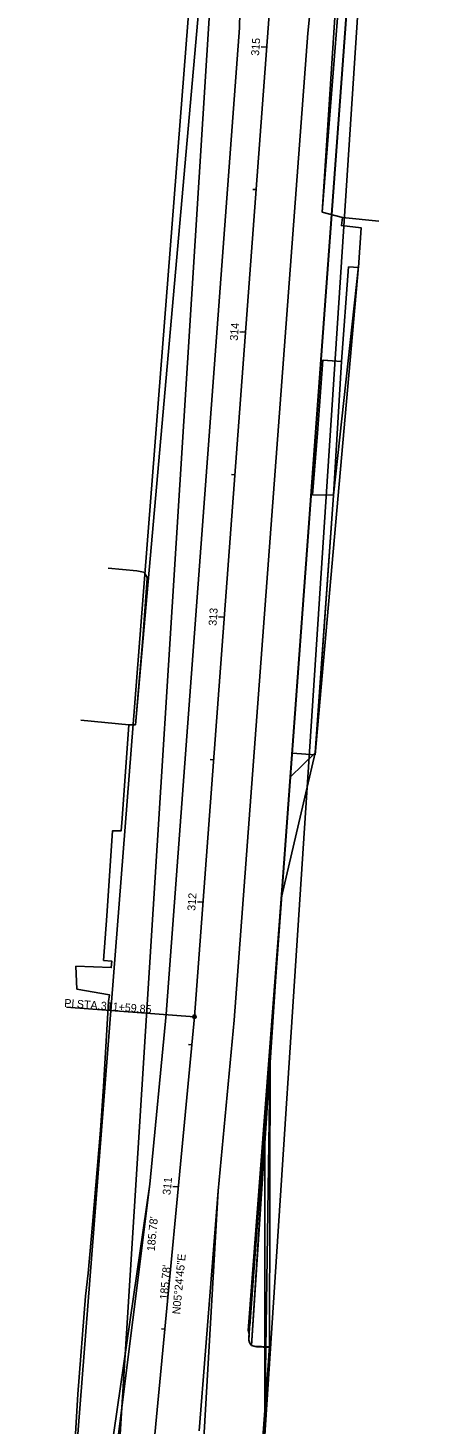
# Model space of a CAD drawing. Extents: x 219353 to 221640, y 361458 to 364236.
# Drawn here: x 220538 to 220684.5, y 362474.7 to 362963.2 of the extents above; entities that cross this region are included whole.
import ezdxf

# ---------------------------------------------------------------- set-up
doc = ezdxf.new("R2010")
doc.units = 0
for name, color, linetype in [('Default', 7, 'Continuous'), ('DR_P_Cells', 7, 'Continuous'), ('DR_P_GenericNode', 7, 'Continuous'), ('DR_X_Cells', 7, 'Continuous'), ('DR_X_GenericNode', 7, 'Continuous'), ('DT_X_Contour_Major', 7, 'Continuous'), ('DT_X_Contour_Minor', 7, 'Continuous'), ('DT_X_Terrain_Boundary', 7, 'Continuous'), ('DT_X_Void', 7, 'Continuous'), ('SC_ProfileRun1', 7, 'Continuous'), ('SC_ProfileRun2', 7, 'Continuous'), ('SC_ProfileRun3', 7, 'Continuous'), ('SC_Scratch1', 7, 'Continuous'), ('UT_X_Sanitary_Cells', 7, 'Continuous')]:
    doc.layers.add(name, color=color, linetype=linetype)

msp = doc.modelspace()

# ---------------------------------------------------------------- linework, layer by layer
at = {"layer": 'Default'}
for p, q in [((220606.11, 362243.12), (220684.52, 363442.47)), ((220684.52, 363442.47), (220615.71, 362509.09)), ((220624.82, 362631.32), (220684.52, 363442.47)), ((220684.52, 363442.47), (220626.15, 362649.27)), ((220641.07, 362898.72), (220684.52, 363442.47)), ((220648.26, 362896.8), (220641.07, 362898.72)), ((220647.83, 362894.02), (220648.26, 362896.8)), ((220654.81, 362893.19), (220647.83, 362894.02)), ((220653.82, 362879.4), (220654.81, 362893.19)), ((220638.7, 362708.88), (220653.85, 362879.85)), ((220653.85, 362879.85), (220645.02, 362799.67)), ((220647.88, 362846.46), (220650.36, 362879.59)), ((220650.36, 362879.59), (220653.82, 362879.4)), ((220645.02, 362799.67), (220647.88, 362846.46)), ((220638.7, 362709.51), (220626.88, 362659.06)), ((220626.88, 362659.06), (220630.64, 362709.49)), ((220630.02, 362701.13), (220638.7, 362709.51)), ((220630.64, 362709.49), (220638.7, 362708.88)), ((220615.19, 362507.4), (220630.02, 362701.13)), ((220626.15, 362649.27), (220615.19, 362507.4)), ((220616.32, 362502.25), (220624.82, 362631.32)), ((220622.88, 362604.84), (220616.32, 362502.25)), ((220621, 362477.12), (220622.88, 362604.84)), ((220622.88, 362604.84), (220622.7, 362501.72)), ((220622.7, 362501.72), (220622.88, 362604.84)), ((220615.71, 362509.09), (220620.96, 362579.91)), ((220620.96, 362579.91), (220621, 362477.12)), ((220615.41, 362504.1), (220615.41, 362505.1))]:
    msp.add_line(p, q, dxfattribs=at)
msp.add_open_spline([(220615.41, 362505.04), (220615.36, 362504.35), (220615.42, 362503.13), (220616.86, 362501.84), (220617.84, 362501.8), (220618.19, 362501.78)], degree=3, dxfattribs=at)
at = {"layer": 'DR_X_Cells'}
msp.add_line((220596.38, 362617.24), (220551.5, 362620.59), dxfattribs=at)
msp.add_circle((220596.38, 362617.24), 0.6, dxfattribs=at)
at = {"layer": 'DR_X_GenericNode'}
for p, q in [((220631.67, 363446.41), (220538.01, 362247.29)), ((220541.47, 362010.88), (220631.67, 363446.41)), ((220612.16, 362963.18), (220613.87, 363053.31)), ((220575.71, 362719.33), (220605.02, 363051.24)), ((220636.09, 362961.4), (220644.78, 363051)), ((220641.07, 362898.72), (220646.21, 362977.69)), ((220586.41, 362618.09), (220612.16, 362963.18)), ((220610.33, 362616.06), (220636.09, 362961.4)), ((220648.26, 362896.8), (220641.07, 362898.72)), ((220647.83, 362894.02), (220648.26, 362896.8)), ((220654.81, 362893.19), (220647.83, 362894.02)), ((220653.82, 362879.4), (220654.81, 362893.19)), ((220647.88, 362846.46), (220650.36, 362879.59)), ((220650.36, 362879.59), (220653.82, 362879.4)), ((220645.02, 362799.67), (220647.88, 362846.46)), ((220638.7, 362709.51), (220645.02, 362799.67)), ((220573.39, 362719.33), (220575.71, 362719.33)), ((220626.88, 362659.06), (220630.64, 362709.49)), ((220630.64, 362709.49), (220638.7, 362708.88)), ((220638.7, 362708.88), (220638.7, 362709.51)), ((220622.88, 362604.84), (220626.88, 362659.06)), ((220580.78, 362558.61), (220586.41, 362618.09)), ((220604.67, 362556.35), (220610.33, 362616.06)), ((220618.61, 362547.99), (220622.88, 362604.84)), ((220562.63, 362433.83), (220580.78, 362558.61)), ((220598.01, 362472.29), (220604.67, 362556.35)), ((220615.19, 362507.4), (220618.61, 362547.99)), ((220615.49, 362506.1), (220615.19, 362507.4)), ((220615.41, 362504.1), (220615.49, 362506.1)), ((220615.76, 362503.06), (220615.41, 362504.1)), ((220616.32, 362502.25), (220615.76, 362503.06)), ((220617.16, 362501.92), (220616.32, 362502.25)), ((220622.7, 362501.72), (220617.16, 362501.92)), ((220622.58, 362500.41), (220622.7, 362501.72)), ((220621, 362477.12), (220622.58, 362500.41)), ((220615.74, 362408.19), (220621, 362477.12))]:
    msp.add_line(p, q, dxfattribs=at)
at = {"layer": 'DT_X_Contour_Major'}
for p, q in [((220596.38, 362617.24), (220663.15, 363512.27)), ((220577.51, 362418.1), (220596.38, 362617.24)), ((220578.85, 362432.29), (220596.38, 362617.24))]:
    msp.add_line(p, q, dxfattribs=at)
at = {"layer": 'DT_X_Contour_Minor'}
for p, q in [((220636.09, 362961.4), (220644.78, 363051)), ((220636.09, 362961.4), (220644.78, 363051)), ((220586.41, 362618.09), (220612.16, 362963.18)), ((220586.41, 362618.09), (220612.16, 362963.18)), ((220586.41, 362618.09), (220612.16, 362963.18)), ((220586.41, 362618.09), (220612.16, 362963.18)), ((220586.41, 362618.09), (220612.16, 362963.18)), ((220610.33, 362616.06), (220636.09, 362961.4)), ((220610.33, 362616.06), (220636.09, 362961.4)), ((220641.59, 362846.95), (220647.88, 362846.46)), ((220645.02, 362799.67), (220637.73, 362799.78)), ((220638.65, 362708.89), (220645.02, 362799.67)), ((220638.65, 362708.89), (220645.02, 362799.67)), ((220628.86, 362685.48), (220630.64, 362709.49)), ((220628.86, 362685.48), (220630.64, 362709.49)), ((220630.64, 362709.49), (220638.65, 362708.89)), ((220630.64, 362709.49), (220638.65, 362708.89)), ((220626.88, 362659.06), (220628.86, 362685.48)), ((220626.88, 362659.06), (220628.86, 362685.48)), ((220624.82, 362631.32), (220626.88, 362659.06)), ((220624.82, 362631.32), (220626.88, 362659.06)), ((220555.18, 362626.91), (220554.83, 362634.86)), ((220622.94, 362605.57), (220624.82, 362631.32)), ((220622.94, 362605.57), (220624.82, 362631.32)), ((220580.78, 362558.61), (220586.41, 362618.09)), ((220580.78, 362558.61), (220586.41, 362618.09)), ((220580.78, 362558.61), (220586.41, 362618.09)), ((220580.78, 362558.61), (220586.41, 362618.09)), ((220580.78, 362558.61), (220586.41, 362618.09)), ((220604.67, 362556.35), (220610.33, 362616.06)), ((220604.67, 362556.35), (220610.33, 362616.06)), ((220620.96, 362579.87), (220622.94, 362605.57)), ((220620.96, 362579.87), (220622.94, 362605.57)), ((220618.81, 362550.62), (220620.96, 362579.87)), ((220618.81, 362550.62), (220620.96, 362579.87)), ((220564.94, 362433.61), (220580.78, 362558.61)), ((220564.94, 362433.61), (220580.78, 362558.61)), ((220564.94, 362433.61), (220580.78, 362558.61)), ((220564.94, 362433.61), (220580.78, 362558.61)), ((220564.94, 362433.61), (220580.78, 362558.61)), ((220597.41, 362430.53), (220604.67, 362556.35)), ((220597.41, 362430.53), (220604.67, 362556.35)), ((220597.41, 362430.53), (220604.67, 362556.35)), ((220616.97, 362525.97), (220618.81, 362550.62)), ((220616.97, 362525.97), (220618.81, 362550.62)), ((220615.41, 362505.04), (220616.97, 362525.97)), ((220615.41, 362505.04), (220616.97, 362525.97)), ((220615.12, 362399.96), (220622.66, 362501.46)), ((220615.12, 362399.96), (220622.66, 362501.46)), ((220622.66, 362501.46), (220618.19, 362501.78)), ((220622.66, 362501.46), (220618.19, 362501.78))]:
    msp.add_line(p, q, dxfattribs=at)
for points in [[(220647.88, 362846.46), (220650.36, 362879.59), (220653.82, 362879.4), (220654.81, 362893.19), (220647.83, 362894.02), (220648.26, 362896.8), (220660.9, 362895.52)], [(220647.88, 362846.46), (220650.36, 362879.59), (220653.82, 362879.4), (220654.81, 362893.19), (220647.83, 362894.02), (220648.26, 362896.8), (220660.9, 362895.52)], [(220645.02, 362799.67), (220637.73, 362799.78), (220639.47, 362821.44), (220641.35, 362846.97), (220647.88, 362846.46)], [(220554.83, 362634.86), (220567.24, 362634.42), (220567.45, 362636.61), (220564.51, 362636.9), (220565.68, 362652.52), (220567.69, 362682.29), (220570.73, 362682.29), (220571.06, 362686.6), (220573.39, 362719.33), (220556.55, 362721.02)], [(220548.97, 362401.87), (220551.9, 362425.19), (220552.11, 362427.73), (220555.49, 362485.14), (220558.19, 362519.47), (220559.13, 362527.53), (220560.7, 362544.5), (220563.39, 362577.56), (220564.51, 362592.82), (220566.29, 362622.53), (220566.62, 362624.87), (220555.18, 362626.91)]]:
    msp.add_lwpolyline(points, dxfattribs=at)
msp.add_open_spline([(220618.19, 362501.78), (220617.84, 362501.8), (220616.86, 362501.84), (220615.42, 362503.13), (220615.36, 362504.35), (220615.41, 362505.04)], degree=3, dxfattribs=at)
msp.add_open_spline([(220618.19, 362501.78), (220617.84, 362501.8), (220616.86, 362501.84), (220615.42, 362503.13), (220615.36, 362504.35), (220615.41, 362505.04)], degree=3, dxfattribs=at)
at = {"layer": 'DT_X_Terrain_Boundary'}
for p, q in [((220576.19, 362773.22), (220566.19, 362774.13)), ((220578.5, 362772.75), (220576.19, 362773.22)), ((220578.29, 362749.55), (220579.83, 362770.51)), ((220575.71, 362719.33), (220578.29, 362749.55))]:
    msp.add_line(p, q, dxfattribs=at)
msp.add_ellipse((220575.86, 362769.63), major_axis=(2.06, 3.53), ratio=0.992635, start_param=5.454232, end_param=6.106412, dxfattribs=at)
at = {"layer": 'DT_X_Void'}
for p, q in [((220630.64, 362709.49), (220628.86, 362685.48)), ((220628.86, 362685.48), (220626.88, 362659.06)), ((220626.88, 362659.06), (220624.82, 362631.32)), ((220624.82, 362631.32), (220622.94, 362605.57)), ((220622.94, 362605.57), (220620.96, 362579.87)), ((220620.96, 362579.87), (220618.81, 362550.62)), ((220618.81, 362550.62), (220616.97, 362525.97)), ((220616.97, 362525.97), (220615.41, 362505.04)), ((220618.19, 362501.78), (220622.66, 362501.46))]:
    msp.add_line(p, q, dxfattribs=at)
at = {"layer": 'SC_ProfileRun2'}
msp.add_line((220596.38, 362617.24), (220551.5, 362620.59), dxfattribs=at)
msp.add_circle((220596.38, 362617.24), 0.6, dxfattribs=at)
at = {"layer": 'SC_ProfileRun3'}
for p, q in [((220621.69, 362956.46), (220619.69, 362956.61)), ((220614.25, 362856.73), (220613.05, 362856.82)), ((220606.81, 362757.01), (220605.61, 362757.1)), ((220599.37, 362657.29), (220598.17, 362657.38)), ((220590.73, 362557.67), (220589.54, 362557.78))]:
    msp.add_line(p, q, dxfattribs=at)
at = {"layer": 'UT_X_Sanitary_Cells'}
for p, q in [((220621.69, 362956.46), (220619.69, 362956.61)), ((220617.97, 362906.6), (220616.77, 362906.68)), ((220614.25, 362856.73), (220612.25, 362856.88)), ((220610.53, 362806.87), (220609.33, 362806.96)), ((220606.81, 362757.01), (220604.81, 362757.16)), ((220603.09, 362707.15), (220601.89, 362707.24)), ((220599.37, 362657.29), (220597.37, 362657.44)), ((220595.45, 362607.44), (220594.25, 362607.56)), ((220590.73, 362557.67), (220588.74, 362557.85)), ((220586.02, 362507.89), (220584.82, 362508))]:
    msp.add_line(p, q, dxfattribs=at)

# ---------------------------------------------------------------- texts
at = {"layer": 'DR_P_Cells'}
msp.add_text("185.78'", height=2.8, rotation=84.5875, dxfattribs=at).set_placement((220586.94, 362518.12))
at = {"layer": 'DR_P_GenericNode'}
msp.add_text("185.78'", height=2.8, rotation=84.5875, dxfattribs=at).set_placement((220582.43, 362535.07))
at = {"layer": 'DR_X_Cells'}
for s, p in [('PI', (220550.66, 362620.7)), (' STA. ', (220554.04, 362620.45)), ('311+59.85', (220563.46, 362619.74))]:
    msp.add_text(s, height=2.8, rotation=355.7333, dxfattribs=at).set_placement(p)
at = {"layer": 'SC_ProfileRun1'}
msp.add_text('N05°24\'45"E', height=2.8, rotation=84.5875, dxfattribs=at).set_placement((220591.32, 362513))
at = {"layer": 'SC_ProfileRun2'}
for s, p in [('PI', (220550.66, 362620.7)), (' STA. ', (220554.04, 362620.45)), ('311+59.85', (220563.46, 362619.74))]:
    msp.add_text(s, height=2.8, rotation=355.7333, dxfattribs=at).set_placement(p)
at = {"layer": 'SC_ProfileRun3'}
msp.add_text('315', height=2.8, rotation=85.7333, dxfattribs=at).set_placement((220618.95, 362953.35))
at = {"layer": 'SC_Scratch1'}
msp.add_text('N05°24\'45"E', height=2.8, rotation=84.5875, dxfattribs=at).set_placement((220591.32, 362513))
at = {"layer": 'UT_X_Sanitary_Cells'}
for s, rotation, p in [('315', 85.7333, (220618.95, 362953.35)), ('314', 85.7333, (220611.51, 362853.66)), ('313', 85.7333, (220604.07, 362753.93)), ('312', 85.7333, (220596.63, 362654.2)), ('311', 84.5875, (220587.95, 362554.76))]:
    msp.add_text(s, height=2.8, rotation=rotation, dxfattribs=at).set_placement(p)

doc.saveas('drawing.dxf')
